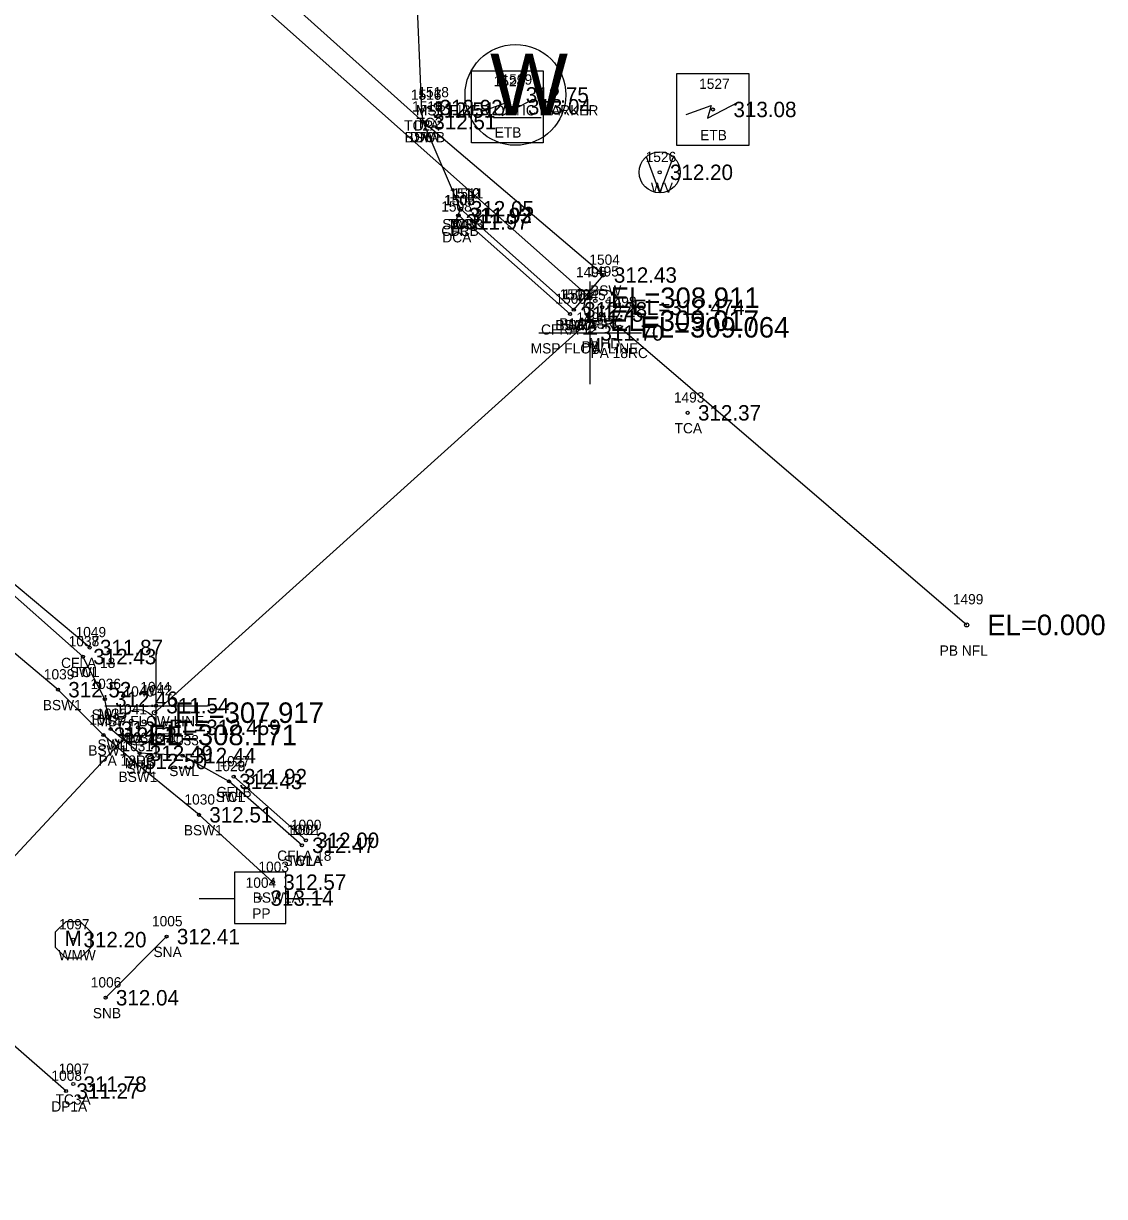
# Model space of a CAD drawing. Extents: x 1970076 to 1971136, y 803126 to 804215.
# Drawn here: x 1970967.7 to 1971072.9, y 803129.3 to 803243.6 of the extents above; entities that cross this region are included whole.
import ezdxf

# ---------------------------------------------------------------- set-up
doc = ezdxf.new("R2010")
doc.units = 0
for name, color, linetype in [('RD_EX_BldgApp', 7, 'Continuous'), ('RD_EX_BldgApp_txCode', 7, 'Continuous'), ('RD_EX_Conc', 7, 'Continuous'), ('RD_EX_Conc_txCode', 7, 'Continuous'), ('RD_EX_DR_Inlet', 7, 'Continuous'), ('RD_EX_DR_Inlet_txCode', 7, 'Continuous'), ('RD_EX_DR_Pipe', 7, 'Continuous'), ('RD_EX_DR_Pipe_txCode', 7, 'Continuous'), ('RD_EX_Driveway', 7, 'Continuous'), ('RD_EX_Driveway_txCode', 7, 'Continuous'), ('RD_EX_Misc', 7, 'Continuous'), ('RD_EX_Misc_txCode', 7, 'Continuous'), ('RD_EX_SU_H2O', 7, 'Continuous'), ('RD_EX_TX_BldgApp_ELEV', 7, 'Continuous'), ('RD_EX_TX_Conc_ELEV', 7, 'Continuous'), ('RD_EX_TX_DR_Inlet_ELEV', 7, 'Continuous'), ('RD_EX_TX_Driveway_ELEV', 7, 'Continuous'), ('RD_EX_TX_Misc_ELEV', 7, 'Continuous'), ('RD_EX_TX_UT_ELEV', 7, 'Continuous'), ('RD_EX_UT', 7, 'Continuous'), ('RD_EX_UT_txCode', 7, 'Continuous'), ('RD_HC_Survey_ELEV', 7, 'Continuous'), ('RD_SMD_Locator', 7, 'Continuous'), ('RD_TX_Pipe_ElevEX', 7, 'Continuous')]:
    doc.layers.add(name, color=color, linetype=linetype)

msp = doc.modelspace()

# ---------------------------------------------------------------- linework, layer by layer
at = {"layer": 'RD_EX_BldgApp'}
msp.add_line((1970981.62, 803154.62), (1970975.69, 803148.66), dxfattribs=at)
at = {"layer": 'RD_EX_Conc'}
for p, q in [((1971021.27, 803215.68), (1971010.25, 803225.52)), ((1971020.9, 803215.26), (1971010.07, 803224.87)), ((1970995.18, 803164), (1970988.16, 803170.2))]:
    msp.add_line(p, q, dxfattribs=at)
for points in [[(1971009.74, 803224.24), (1971010.01, 803224.85), (1971010.25, 803225.52), (1971006.59, 803233.99), (1970934.65, 803298.46), (1970929.07, 803297.51), (1970928.19, 803297.32), (1970927.5, 803297.02)], [(1971021.27, 803215.68), (1971024.17, 803219.06), (1971006.59, 803233.99)], [(1970991.98, 803159.92), (1970984.78, 803166.48), (1970978.42, 803171.68), (1970975.48, 803174.25), (1970971.05, 803178.67), (1970952.67, 803194.12), (1970948.25, 803197.98), (1970937.76, 803206.39), (1970938.1, 803207.37)], [(1970994.79, 803163.51), (1970987.7, 803169.73), (1970983.17, 803172.25), (1970978.99, 803172.48), (1970976.18, 803174.83), (1970975.61, 803177.74), (1970973.48, 803181.89), (1970955.71, 803197.61), (1970950.79, 803201.04), (1970951.1, 803202.14), (1970938.1, 803207.37)], [(1970974.14, 803182.78), (1970955.99, 803197.96), (1970950.97, 803201.14)]]:
    msp.add_lwpolyline(points, dxfattribs=at)
at = {"layer": 'RD_EX_DR_Inlet'}
for centre, radius in [((1971024.03, 803215.92), 1.75), ((1971023.36, 803216.55), 0.175), ((1971024.59, 803216.48), 0.175), ((1971023.94, 803215.26), 0.175), ((1970978.85, 803175), 1.75), ((1970978.19, 803175.63), 0.175), ((1970979.41, 803175.56), 0.175), ((1970978.77, 803174.33), 0.175)]:
    msp.add_circle(centre, radius, dxfattribs=at)
at = {"layer": 'RD_EX_DR_Pipe'}
for p, q in [((1971022.85, 803216.85), (1970817.34, 803399.52)), ((1970980.44, 803176.43), (1971022.79, 803214.61)), ((1971025.75, 803213.97), (1971059.52, 803184.98)), ((1970977.83, 803174.26), (1970935.85, 803129.3))]:
    msp.add_line(p, q, dxfattribs=at)
at = {"layer": 'RD_EX_Driveway'}
for points in [[(1971006.59, 803233.99), (1971006.48, 803235.13), (1971005.93, 803248.07), (1971009.82, 803263.37), (1971020.47, 803277.61), (1971035.79, 803290.96)], [(1970971.84, 803139.57), (1970941.59, 803165.98), (1970933.19, 803161.96), (1970929.41, 803160.69), (1970902.05, 803185.25), (1970901.29, 803185.97), (1970900.63, 803185.94), (1970885.6, 803170.52)]]:
    msp.add_lwpolyline(points, dxfattribs=at)
at = {"layer": 'RD_EX_Misc'}
for p, q in [((1971022.86, 803208.42), (1971022.86, 803218.42)), ((1971017.86, 803213.42), (1971027.86, 803213.42)), ((1970980.6, 803172.11), (1970980.6, 803182.11)), ((1970975.6, 803177.11), (1970985.6, 803177.11))]:
    msp.add_line(p, q, dxfattribs=at)
at = {"layer": 'RD_EX_SU_H2O'}
msp.add_lwpolyline([(1970974.28, 803153.59), (1970974.28, 803155.04), (1970973.25, 803156.07), (1970971.8, 803156.07), (1970970.77, 803155.04), (1970970.77, 803153.59), (1970971.8, 803152.56), (1970973.25, 803152.56)], close=True, dxfattribs=at)
at = {"layer": 'RD_EX_UT'}
for p, q in [((1971013.46, 803234.4), (1971018.09, 803234.4)), ((1971029.63, 803227.08), (1971028.33, 803230.56)), ((1971029.63, 803227.08), (1971030.95, 803230.52)), ((1970993.24, 803160.88), (1970988.24, 803160.88)), ((1970988.24, 803160.88), (1970988.24, 803155.88)), ((1970993.24, 803155.88), (1970993.24, 803160.88)), ((1970984.8, 803158.32), (1970988.27, 803158.32)), ((1970993.16, 803158.32), (1970996.8, 803158.32)), ((1970988.24, 803155.88), (1970993.24, 803155.88))]:
    msp.add_line(p, q, dxfattribs=at)
for points in [[(1971011.3, 803231.95), (1971011.3, 803238.95), (1971018.3, 803238.95), (1971018.3, 803231.95)], [(1971031.31, 803231.69), (1971031.31, 803238.69), (1971038.31, 803238.69), (1971038.31, 803231.69)]]:
    msp.add_lwpolyline(points, close=True, dxfattribs=at)
for points in [[(1971012.2, 803234.95), (1971014.63, 803235.85), (1971014.28, 803234.6), (1971017.32, 803236.19)], [(1971032.21, 803234.69), (1971034.64, 803235.59), (1971034.29, 803234.34), (1971037.33, 803235.94)]]:
    msp.add_lwpolyline(points, dxfattribs=at)
for centre, radius in [((1971015.59, 803236.61), 4.91), ((1971029.63, 803229.07), 2)]:
    msp.add_circle(centre, radius, dxfattribs=at)
at = {"layer": 'RD_SMD_Locator'}
for centre, radius in [((1971007.2, 803235.38), 0.15), ((1971014.8, 803235.45), 0.15), ((1971006.48, 803235.13), 0.15), ((1971006.48, 803235.13), 0.15), ((1971034.81, 803235.19), 0.15), ((1971006.59, 803233.99), 0.15), ((1971006.59, 803233.99), 0.15), ((1971006.59, 803233.99), 0.15), ((1971029.63, 803229.07), 0.15), ((1971010.25, 803225.52), 0.15), ((1971010.25, 803225.52), 0.15), ((1971010.25, 803225.52), 0.15), ((1971009.74, 803224.24), 0.15), ((1971010.01, 803224.85), 0.15), ((1971010.07, 803224.87), 0.15), ((1971024.17, 803219.06), 0.15), ((1971022.85, 803216.85), 0.2), ((1971024.03, 803215.92), 0.15), ((1971020.9, 803215.26), 0.15), ((1971021.27, 803215.68), 0.15), ((1971021.27, 803215.68), 0.15), ((1971021.27, 803215.68), 0.15), ((1971022.79, 803214.61), 0.2), ((1971025.75, 803213.97), 0.2), ((1971022.86, 803213.42), 0.15), ((1971032.36, 803205.64), 0.15), ((1971059.52, 803184.98), 0.2), ((1970974.14, 803182.78), 0.15), ((1970973.48, 803181.89), 0.15), ((1970973.48, 803181.89), 0.15), ((1970971.05, 803178.67), 0.15), ((1970975.61, 803177.74), 0.15), ((1970980.6, 803177.11), 0.15), ((1970980.44, 803176.43), 0.2), ((1970976.18, 803174.83), 0.15), ((1970978.85, 803175), 0.15), ((1970975.48, 803174.25), 0.15), ((1970977.83, 803174.26), 0.2), ((1970978.99, 803172.48), 0.15), ((1970978.42, 803171.68), 0.15), ((1970983.17, 803172.25), 0.15), ((1970988.16, 803170.2), 0.15), ((1970987.7, 803169.73), 0.15), ((1970987.7, 803169.73), 0.15), ((1970984.78, 803166.48), 0.15), ((1970994.79, 803163.51), 0.15), ((1970994.79, 803163.51), 0.15), ((1970995.18, 803164), 0.15), ((1970991.98, 803159.92), 0.15), ((1970990.74, 803158.37), 0.15), ((1970972.53, 803154.32), 0.15), ((1970981.62, 803154.62), 0.15), ((1970975.69, 803148.66), 0.15), ((1970971.84, 803139.57), 0.15), ((1970972.54, 803140.25), 0.15)]:
    msp.add_circle(centre, radius, dxfattribs=at)

# ---------------------------------------------------------------- texts
at = {"layer": 'RD_EX_BldgApp_txCode'}
for s, p in [('1005', (1970980.2, 803155.62)), ('SNA', (1970980.35, 803152.62)), ('1006', (1970974.24, 803149.66)), ('SNB', (1970974.44, 803146.66))]:
    msp.add_text(s, height=1, dxfattribs=at).set_placement(p)
at = {"layer": 'RD_EX_Conc_txCode'}
for s, p in [('1517', (1971005.42, 803236.13)), ('1518', (1971006.13, 803236.38)), ('1513', (1971005.52, 803234.99)), ('1514', (1971005.52, 803234.99)), ('TC2', (1971005.95, 803233.38)), ('TC2A', (1971004.75, 803233.13)), ('BSWB', (1971004.8, 803231.99)), ('DC', (1971005.81, 803231.99)), ('1510', (1971009.14, 803226.52)), ('1512', (1971009.18, 803226.52)), ('1511', (1971009.47, 803226.52)), ('1509', (1971008.63, 803225.85)), ('1505', (1971008.68, 803225.87)), ('1508', (1971008.36, 803225.24)), ('SWRB', (1971008.46, 803223.52)), ('TCB', (1971008.98, 803223.52)), ('DC', (1971009.47, 803223.52)), ('CFRB', (1971008.37, 803222.87)), ('DCA', (1971008.47, 803222.24)), ('DC', (1971009.23, 803222.85)), ('1504', (1971022.78, 803220.06)), ('1500', (1971019.48, 803216.26)), ('1502', (1971019.89, 803216.68)), ('1503', (1971019.89, 803216.68)), ('1501', (1971020.17, 803216.68)), ('BSW', (1971022.85, 803217.06)), ('CFRA 12', (1971018.08, 803213.26)), ('SWRA', (1971019.47, 803213.68)), ('BSWA', (1971019.47, 803213.68)), ('TC', (1971020.48, 803213.68)), ('1493', (1971031.01, 803206.64)), ('TCA', (1971031.08, 803203.64)), ('1049', (1970972.76, 803183.78)), ('1037', (1970972.09, 803182.89)), ('1038', (1970972.09, 803182.89)), ('CFLA 18', (1970971.35, 803180.78)), ('1039', (1970969.67, 803179.67)), ('SWL', (1970972.19, 803179.89)), ('TC1', (1970972.52, 803179.89)), ('1036', (1970974.21, 803178.74)), ('BSW1', (1970969.57, 803176.67)), ('1032', (1970974.09, 803175.25)), ('SWL', (1970974.32, 803175.74)), ('1035', (1970974.79, 803175.83)), ('SWL', (1970974.89, 803172.83)), ('1034', (1970977.6, 803173.48)), ('1033', (1970981.79, 803173.25)), ('BSW1', (1970974, 803172.25)), ('1031', (1970977.32, 803172.68)), ('SWL', (1970977.7, 803170.48)), ('1028', (1970986.31, 803170.73)), ('1029', (1970986.31, 803170.73)), ('1027', (1970986.77, 803171.2)), ('BSW1', (1970976.94, 803169.68)), ('SWL', (1970981.88, 803170.25)), ('CFLB', (1970986.48, 803168.2)), ('1030', (1970983.36, 803167.48)), ('SWL', (1970986.4, 803167.73)), ('TC1', (1970986.74, 803167.73)), ('1000', (1970993.72, 803165)), ('BSW1', (1970983.3, 803164.48)), ('1002', (1970993.36, 803164.51)), ('1001', (1970993.65, 803164.51)), ('CFLA 18', (1970992.39, 803162)), ('SWLA', (1970993.01, 803161.51)), ('TC1A', (1970993.34, 803161.51)), ('1003', (1970990.56, 803160.92)), ('BSW1A', (1970990.01, 803157.92)), ('1007', (1970971.11, 803141.25)), ('TC3A', (1970970.81, 803138.25))]:
    msp.add_text(s, height=1, dxfattribs=at).set_placement(p)
at = {"layer": 'RD_EX_DR_Inlet_txCode'}
for s, p in [('1495', (1971022.68, 803218.92)), ('MHD', (1971022.74, 803211.92)), ('1040', (1970977.43, 803178)), ('MHD', (1970977.56, 803171))]:
    msp.add_text(s, height=1, dxfattribs=at).set_placement(p)
at = {"layer": 'RD_EX_DR_Pipe_txCode'}
for s, p in [('1496', (1971021.48, 803218.85)), ('1045', (1971021.4, 803216.61)), ('1498', (1971024.4, 803215.97)), ('P1A 18RC', (1971019.84, 803213.85)), ('PB', (1971022.01, 803211.61)), ('PA 18RC', (1971022.9, 803210.97)), ('1499', (1971058.17, 803186.98)), ('PB NFL', (1971056.89, 803181.98)), ('1044', (1970979.06, 803178.43)), ('1041', (1970976.73, 803176.26)), ('PA 18RC', (1970977.6, 803173.43)), ('PA 18RC', (1970974.99, 803171.26))]:
    msp.add_text(s, height=1, dxfattribs=at).set_placement(p)
at = {"layer": 'RD_EX_Driveway_txCode'}
for s, p in [('1516', (1971005.4, 803236.13)), ('1515', (1971005.52, 803234.99)), ('DP', (1971005.7, 803233.13)), ('DPA', (1971005.32, 803231.99)), ('1008', (1970970.41, 803140.57)), ('DP1A', (1970970.4, 803137.57))]:
    msp.add_text(s, height=1, dxfattribs=at).set_placement(p)
at = {"layer": 'RD_EX_Misc_txCode'}
for s, p in [('1529', (1971014.24, 803237.61)), ('MSP FIBER OPTIC MARKER', (1971005.9, 803234.61)), ('1494', (1971021.52, 803214.42)), ('MSP FLOW LINE', (1971017.07, 803211.42)), ('1042', (1970979.21, 803178.11)), ('MSP FLOW LINE', (1970974.8, 803175.11)), ('1097', (1970971.14, 803155.32)), ('WMW', (1970971.09, 803152.32))]:
    msp.add_text(s, height=1, dxfattribs=at).set_placement(p)
at = {"layer": 'RD_EX_SU_H2O'}
msp.add_text('M', height=1.5, dxfattribs=at).set_placement((1970971.69, 803153.71))
at = {"layer": 'RD_EX_TX_BldgApp_ELEV'}
for s, p in [('312.41', (1970982.62, 803153.87)), ('312.04', (1970976.69, 803147.91))]:
    msp.add_text(s, height=1.5, dxfattribs=at).set_placement(p)
at = {"layer": 'RD_EX_TX_Conc_ELEV'}
for s, p in [('312.51', (1971007.48, 803234.38)), ('312.92', (1971008.2, 803234.63)), ('312.51', (1971007.59, 803233.24)), ('312.51', (1971007.59, 803233.24)), ('311.93', (1971011.01, 803224.1)), ('311.92', (1971011.07, 803224.12)), ('312.05', (1971011.25, 803224.77)), ('312.05', (1971011.25, 803224.77)), ('312.05', (1971011.25, 803224.77)), ('311.97', (1971010.74, 803223.49)), ('312.43', (1971025.17, 803218.31)), ('312.28', (1971022.27, 803214.93)), ('312.28', (1971022.27, 803214.93)), ('312.28', (1971022.27, 803214.93)), ('311.75', (1971021.9, 803214.51)), ('312.37', (1971033.36, 803204.89)), ('311.87', (1970975.14, 803182.03)), ('312.43', (1970974.48, 803181.14)), ('312.43', (1970974.48, 803181.14)), ('312.52', (1970972.05, 803177.92)), ('312.46', (1970976.61, 803176.99)), ('312.52', (1970976.48, 803173.5)), ('312.51', (1970977.18, 803174.08)), ('312.49', (1970979.99, 803171.73)), ('312.44', (1970984.17, 803171.5)), ('312.50', (1970979.42, 803170.93)), ('312.43', (1970988.7, 803168.98)), ('312.43', (1970988.7, 803168.98)), ('311.92', (1970989.16, 803169.45)), ('312.51', (1970985.78, 803165.73)), ('312.00', (1970996.18, 803163.25)), ('312.47', (1970995.79, 803162.76)), ('312.47', (1970995.79, 803162.76)), ('312.57', (1970992.98, 803159.17)), ('311.78', (1970973.54, 803139.5))]:
    msp.add_text(s, height=1.5, dxfattribs=at).set_placement(p)
at = {"layer": 'RD_EX_TX_DR_Inlet_ELEV'}
for s, p in [('EL=312.474', (1971027.03, 803215.17)), ('EL=312.459', (1970981.85, 803174.25))]:
    msp.add_text(s, height=1.5, dxfattribs=at).set_placement(p)
at = {"layer": 'RD_EX_TX_Driveway_ELEV'}
for s, p in [('312.51', (1971007.48, 803234.38)), ('312.51', (1971007.59, 803233.24)), ('311.27', (1970972.84, 803138.82))]:
    msp.add_text(s, height=1.5, dxfattribs=at).set_placement(p)
at = {"layer": 'RD_EX_TX_Misc_ELEV'}
for s, p in [('312.75', (1971016.59, 803235.86)), ('311.70', (1971023.86, 803212.67)), ('311.54', (1970981.6, 803176.36)), ('312.20', (1970973.53, 803153.57))]:
    msp.add_text(s, height=1.5, dxfattribs=at).set_placement(p)
at = {"layer": 'RD_EX_TX_UT_ELEV'}
for s, p in [('313.04', (1971016.8, 803234.7)), ('313.08', (1971036.81, 803234.44)), ('312.20', (1971030.63, 803228.32))]:
    msp.add_text(s, height=1.5, dxfattribs=at).set_placement(p)
at = {"layer": 'RD_EX_UT'}
msp.add_text('W', height=6, dxfattribs=at).set_placement((1971013.12, 803234.61))
at = {"layer": 'RD_EX_UT_txCode'}
for s, p in [('1528', (1971013.46, 803237.45)), ('1527', (1971033.47, 803237.19)), ('ETB', (1971013.56, 803232.45)), ('ETB', (1971033.57, 803232.19)), ('1526', (1971028.26, 803230.07)), ('WV', (1971028.77, 803227.07)), ('1004', (1970989.32, 803159.37)), ('PP', (1970989.96, 803156.37))]:
    msp.add_text(s, height=1, dxfattribs=at).set_placement(p)
at = {"layer": 'RD_HC_Survey_ELEV'}
msp.add_text('313.14', height=1.5, dxfattribs=at).set_placement((1970991.74, 803157.62))
at = {"layer": 'RD_TX_Pipe_ElevEX'}
for s, p in [('EL=308.911', (1971024.85, 803215.85)), ('EL=309.017', (1971024.79, 803213.61)), ('EL=309.064', (1971027.75, 803212.97)), ('EL=0.000', (1971061.52, 803183.98)), ('EL=307.917', (1970982.44, 803175.43)), ('EL=308.171', (1970979.83, 803173.26))]:
    msp.add_text(s, height=2, dxfattribs=at).set_placement(p)

doc.saveas('drawing.dxf')
